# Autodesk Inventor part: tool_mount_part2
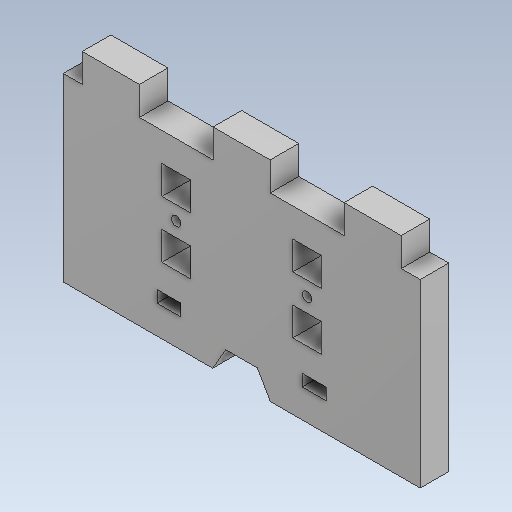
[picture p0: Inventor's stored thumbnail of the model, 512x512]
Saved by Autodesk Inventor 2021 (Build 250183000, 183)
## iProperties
Created: 2026-10
Part Number: tool_mount_part2
Material: Steel
Document SubType Name: Modeling
Designer: hp
Density: 7.85 g/cm^3
Appearance: Default
Author: hp
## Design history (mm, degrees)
feature "Body1"
body "Solid1"
